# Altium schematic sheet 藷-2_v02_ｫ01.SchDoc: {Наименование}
size 420 x 297 mm; ApprovedBy: Ермаков; CheckedBy: Ермаков; DrawnBy: Булычев; Engineer: {Инженер}; DocumentNumber: СИЭТ 21.02.110.000 Э3; SheetNumber: 1; SheetTotal: 6; Title1str: Плата Управления; PageSetup: Record=PageOptions|CenterHorizontal=False|CenterVertical=False|PrintScale=0.95|XCorrection=1.00|YCorrection=1.00|PrintKind=2|BorderSize=5000000|LeftOffset=300|BottomOffset=0|Orientation=2|PaperLength=4200|PaperWidth=2970|Scale=100|PaperSource=15|PrintQuality=-1|MediaType=1|DitherType=10|PaperKind=ISO A3|PrintScaleMode=1; Title2str: (ПУ-2); EngineerName: {Инженер}; DocumentType: Схема электрическая принципиальная; DocumentType1str: {Документ}; DocumentType2str: {Документ}
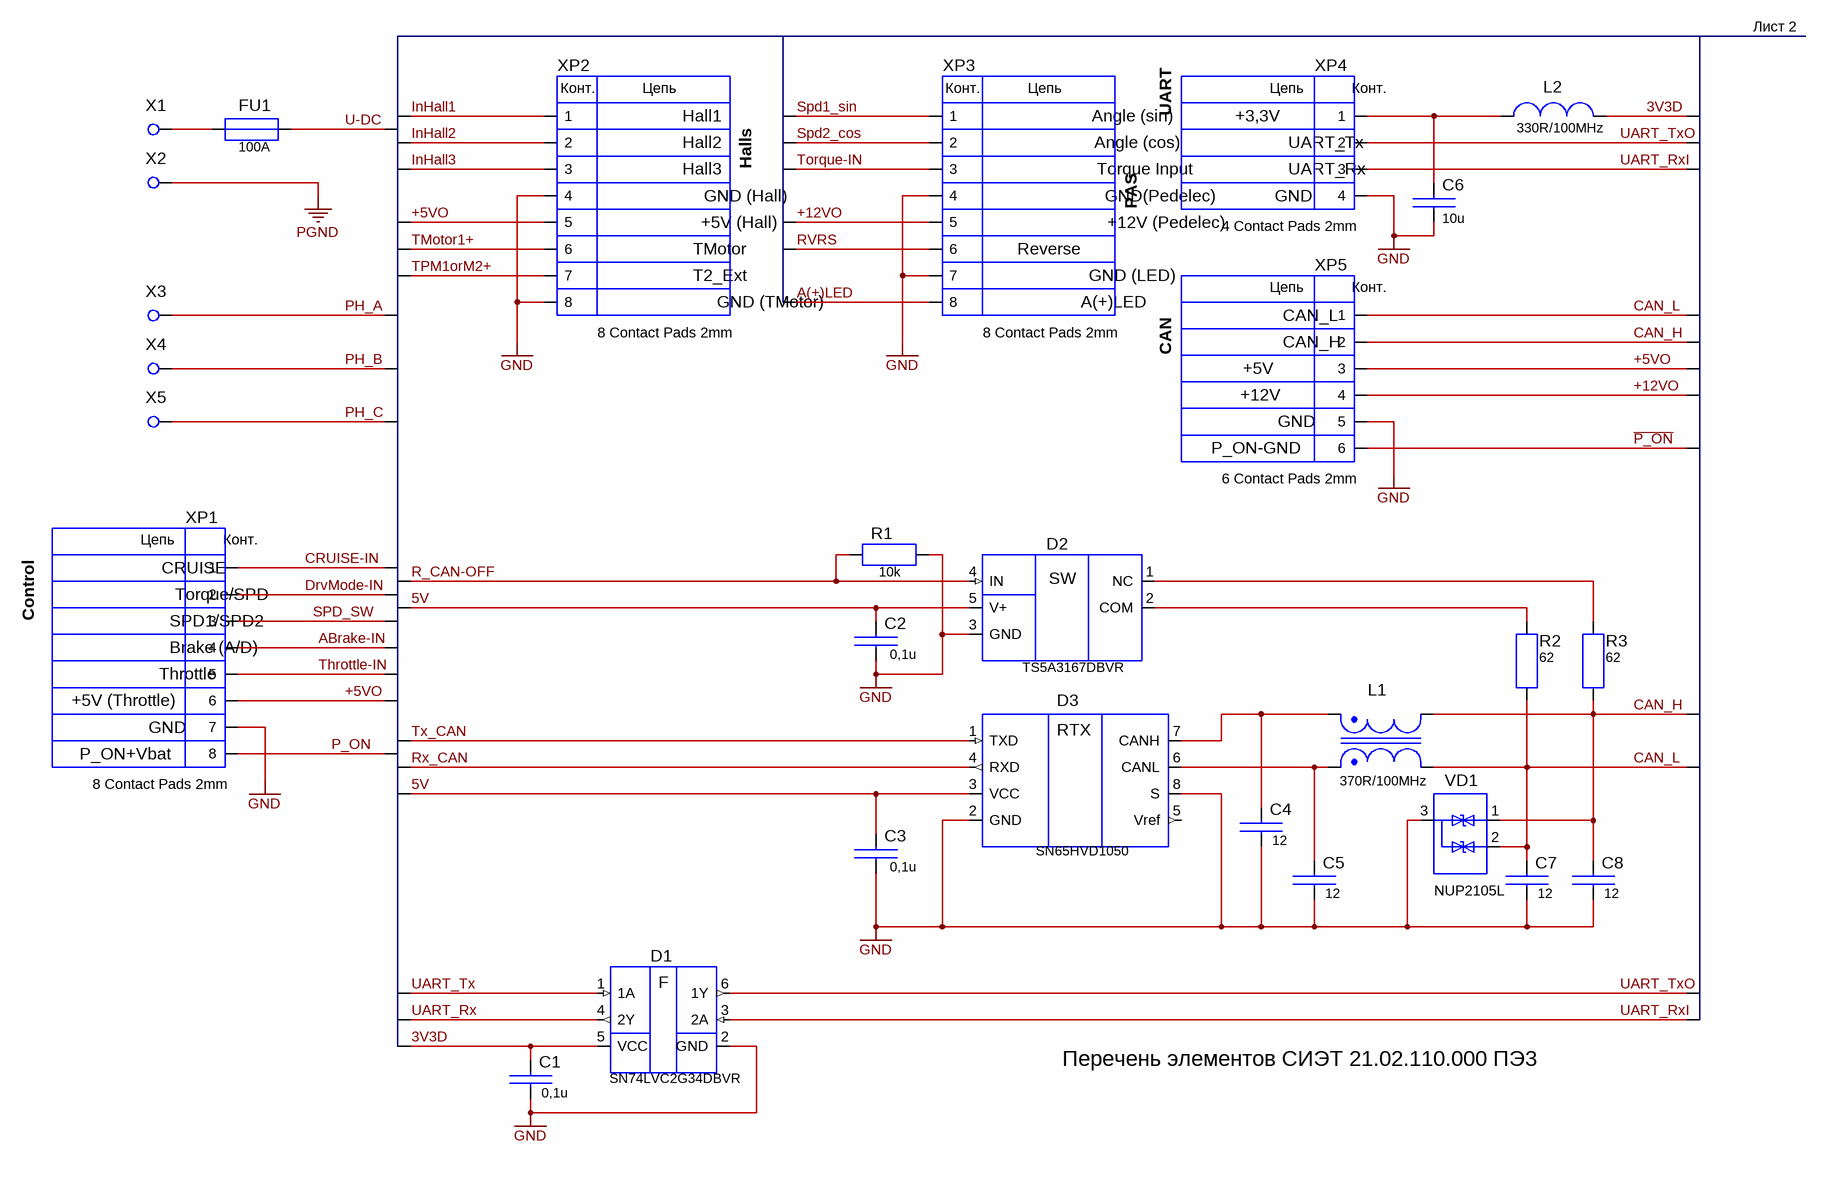
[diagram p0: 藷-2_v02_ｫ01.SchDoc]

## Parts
C1  value 0,1u  [0603]  (hidden comment: CL10B104KB8NNNC)
C2  value 0,1u  [0603]  (hidden comment: CL10B104KB8NNNC)
C3  value 0,1u  [0603]  (hidden comment: CL10B104KB8NNNC)
C4  value 12  [0603]  (hidden comment: CL10C120JB8NNNC)
C5  value 12  [0603]  (hidden comment: CL10C120JB8NNNC)
C6  value 10u  [0603]  (hidden comment: CL10A106MQ8NNNC)
C7  value 12  [0603]  (hidden comment: CL10C120JB8NNNC)
C8  value 12  [0603]  (hidden comment: CL10C120JB8NNNC)
D1  SN74LVC2G34DBVR  [SOT23-6]
D2  TS5A3167DBVR  [SOT23-5]
D3  SN65HVD1050  [SOIC-8]
FU1  100A  [100A_05mmCUfoil]
L1  value 370R/100MHz  [DLW21S]  (hidden comment: DLW21SN371SQ2L)
L2  Impedance@100МHz: 330R/100MHz  [BLM18]  (hidden comment: BLM18PG331SN1D)
R1  value 10k  [RC0603]  (hidden comment: RC0603FR-0710KL)
R2  value 62  [RC0603]  (hidden comment: RC0603FR-0762RL)
R3  value 62  [RC0603]  (hidden comment: RC0603FR-0762RL)
VD1  NUP2105L  [SOT-23]
X1  Pad-AWG10  [Pad-AWG10]  (value not drawn)
X2  Pad-AWG10  [Pad-AWG10]  (value not drawn)
X3  Pad-AWG10  [Pad-AWG10]  (value not drawn)
X4  Pad-AWG10  [Pad-AWG10]  (value not drawn)
X5  Pad-AWG10  [Pad-AWG10]  (value not drawn)
XP1  8pin2mm  [8pin2mm]  (value not drawn)  (parts A,B,C,D,E,F,G,H,I of 9)
XP2  8pin2mm  [8pin2mm]  (value not drawn)  (parts A,B,C,D,E,F,G,H,I of 9)
XP3  8pin2mm  [8pin2mm]  (value not drawn)  (parts A,B,C,D,E,F,G,H,I of 9)
XP4  4pin2mm  [4pin2mm]  (value not drawn)  (parts A,B,C,D,E of 5)
XP5  6pin2mm  [6pin2mm]  (value not drawn)  (parts A,B,C,D,E,F,G of 7)

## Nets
GND: C1.1 C2.1 C3.1 C4.1 C5.1 C6.2 C7.1 C8.1 D1.2(GND) D2.3(GND) D3.2(GND) D3.8(S) R1.2 VD1.3 XP1.7 XP2.4 XP2.8 XP3.4 XP3.7 XP4.4 XP5.5
PGND: X2.1
3V3D: C1.2 D1.5(VCC) L2.1
5V: C2.2 C3.2 D2.5(V+) D3.3(VCC)
+5VO: XP1.6 XP2.5 XP5.3
+12VO: XP3.5 XP5.4
~{P_ON}: XP5.6
A(+)LED: XP3.8
ABrake-IN: XP1.4
CAN_H: C8.2 L1.2 R3.2 VD1.1 XP5.2
CAN_L: C7.2 L1.3 R2.2 VD1.2 XP5.1
CRUISE-IN: XP1.1
DrvMode-IN: XP1.2
InHall1: XP2.1
InHall2: XP2.2
InHall3: XP2.3
P_ON: XP1.8
PH_A: X3.1
PH_B: X4.1
PH_C: X5.1
R_CAN-OFF: D2.4(IN) R1.1
RVRS: XP3.6
Rx_CAN: D3.4(RXD)
Spd1_sin: XP3.1
Spd2_cos: XP3.2
SPD_SW: XP1.3
Throttle-IN: XP1.5
TMotor1+: XP2.6
Torque-IN: XP3.3
TPM1orM2+: XP2.7
Tx_CAN: D3.1(TXD)
U-DC: FU1.2
UART_Rx: D1.4(2Y)
UART_RxI: D1.3(2A) XP4.3
UART_Tx: D1.1(1A)
UART_TxO: D1.6(1Y) XP4.2
NetC4_2: C4.2 D3.7(CANH) L1.1
NetC5_2: C5.2 D3.6(CANL) L1.4
NetC6_1: C6.1 L2.2 XP4.1
NetD2_1: D2.1(NC) R3.1
NetD2_2: D2.2(COM) R2.1
NetFU1_1: FU1.1 X1.1

Not connected (* = marked no-connect by the designer): D3 5(Vref)

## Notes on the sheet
- Лист 2
- (near XP2) XP2
- Hall1
- (near XP3) XP3
- Angle (sin)
- UART
- +3,3V
- (near XP4) XP4
- Hall3
- Hall2
- GND (Hall)
- Halls
- Angle (cos)
- (near XP3) Torque Input
- GND(Pedelec)
- PAS
- GND
- UART_Tx
- UART_Rx
- TMotor
- +5V (Hall)
- Reverse
- (near XP3) +12V (Pedelec)
- (near XP5) XP5
- T2_Ext
- GND (TMotor)
- A(+)LED
- GND (LED)
- CAN_L
- CAN
- +12V
- +5V
- CAN_H
- P_ON-GND
- (near XP1) XP1
- CRUISE
- (near XP1) Torque/SPD
- Control
- SPD1/SPD2
- Brake (A/D)
- (near XP1) +5V (Throttle)
- Throttle
- P_ON+Vbat
- Перечень элементов СИЭТ 21.02.110.000 ПЭ3

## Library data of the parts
C1-C3 = CL10B104KB8NNNC: 0603 - 50V - 0,1uF; Pdf: GeneralCapacitors_12022.pdf; Voltage: 50В; Type: CL10; Tolerance: ±10%; ТКЕ: X7R
C4 C5 C7 C8 = CL10C120JB8NNNC: 0603 - 50V - 12pF; Pdf: GeneralCapacitors_12022.pdf; Voltage: 50В; Type: CL10; Tolerance: ±5%; ТКЕ: NP0
C6 = CL10A225KP8NNNC: 0603, 10V, 2.2uF; Pdf: GeneralCapacitors_12022.pdf; Voltage: 6,3В; Type: CL10; Tolerance: ±10%; ТКЕ: X5R
D1 = SN74LVC2G34DBVR: Dual Buffer Gate; Корпус: SOT-23-6; Установка: VIб/6Д0.673.003Д с.32ж
D2 = TS5A3167DBVR: 0.9 Ohm SPST ANALOG SWITCH; Корпус: SOT-23-5; Установка: VIб/6Д0.673.003Д с.32ж
D3 = SN65HVD1050: EMC OPTIMIZED CAN TRANSCEIVER; Type: SN65HVD1050D; Корпус: SO-8; Установка: VIб/6Д0.673.003Д с.32ж
FU1 = 100A_05mmCU: 100A предохранитель из фольги 0,5мм; Pdf: 466.pdf; Корпус: 1206; Climate: -55 +125; Resistance: * Ом; Vmax: 100Vdc
L1 = DLW21SN371SQ2L: Chip Common Mode Choke Coil; Корпус: 2.0x1.2; Pdf: EFLC0003.pdf
L2 = BLM18PG331SN1D: EMI Suppression Filter; Корпус: 0603; Pdf: Murata BLM.pdf; DCResistance: 0.15
R1-R3 = RC0603: 0603, 0.1W, Thick Film Chip Resistors; Power: 0,1 Вт; Tolerance: ±1%; Pdf: RC0603.pdf; Корпус: 0603; ТКС: ±100 ppm/K
VD1 = NUP2105L: SURFACE MOUNT SWITCHING DIODES; Pdf: NUP2105L.pdf; Корпус: SOT23
X1-X5 = Pad-AWG10: Площадка для запайки провода AWG10; КД: 7460408; Исполнение: под винт М5; Ответная часть: провод AWG8
XP1-XP3 = 8pin2mm: Вилка на плату 8 контактов; Pdf: ENG_CD_1734709_B1.pdf; Исполнение: Header Male Pin; КД: 1-1734709-0; Конт. отв. части (AWG32-28; 0,2-0,32mm): 1734597-1; Ответная часть (обжимка на провод): 1-1470364-0; Замена 1 (Отв. часть на провод): SHR-10V-S; Замена 1: SM10B-SRSS-TB (JST); Замена 2: CI1110M1HR0-NH (CviLux); Замена 2 (Отв. часть на провод): CI1110S0000-NH (CviLux); Замена 1 (Конт. отв. части): SSH-003T-P0.2-H; Замена 2 (Конт. отв. части): CI11T011PP0; Замена 3 (Конт. отв. части): M40-1000046; Замена 3 (Отв. часть на провод): M40-1101000; Замена 3: M40-4011046
XP4 = 4pin2mm: Вилка на плату 4 контакта; Pdf: ENG_CD_1734709_B1.pdf; Исполнение: Header Male Pin; КД: 1734709-4; Конт. отв. части (AWG32-28; 0,2-0,32mm): 1734597-1; Ответная часть (обжимка на провод): 1470364-4; Замена 1 (Отв. часть на провод): SHR-04V-S; Замена 1: SM04B-SRSS-TB (JST); Замена 2: CI1104M1HR0-NH (CviLux); Замена 2 (Отв. часть на провод): CI1104S0000-NH (CviLux); Замена 1 (Конт. отв. части): SSH-003T-P0.2-H; Замена 2 (Конт. отв. части): CI11T011PP0; Замена 3: M40-4010446; Замена 3 (Отв. часть на провод): M40-1100400; Замена 3 (Конт. отв. части): M40-1000046
XP5 = 6pin2mm: Вилка на плату 6 контактов; Pdf: ENG_CD_1734709_B1.pdf; Исполнение: Header Male Pin; КД: 1734709-6; Конт. отв. части (AWG32-28; 0,2-0,32mm): 1734597-1; Ответная часть (обжимка на провод): 1470364-6; Замена 1 (Отв. часть на провод): SHR-06V-S; Замена 1: SM06B-SRSS-TB (JST); Замена 2: CI1106M1HR0-NH (CviLux); Замена 2 (Отв. часть на провод): CI1106S0000-NH (CviLux); Замена 1 (Конт. отв. части): SSH-003T-P0.2-H; Замена 2 (Конт. отв. части): CI11T011PP0; Замена 3: M40-4010646; Замена 3 (Конт. отв. части): M40-1000046; Замена 3 (Отв. часть на провод): M40-1100600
